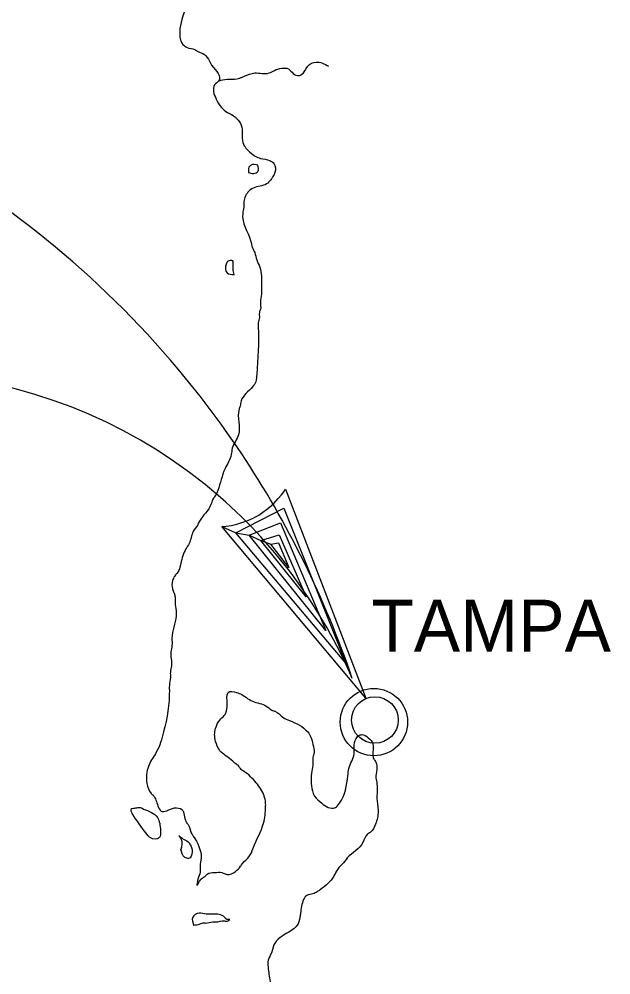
# Model space of a CAD drawing. Extents: x 492225 to 553725, y 1303773 to 1347273.
# Drawn here: x 540852 to 542273, y 1339012 to 1341307 of the extents above; entities that cross this region are included whole.
import ezdxf

# ---------------------------------------------------------------- set-up
doc = ezdxf.new("R2010")
doc.units = 0
for name, color, linetype in [('Level 1', 7, 'Continuous'), ('Level 62', 7, 'Continuous'), ('Level 63', 7, 'Continuous')]:
    doc.layers.add(name, color=color, linetype=linetype)

msp = doc.modelspace()

# ---------------------------------------------------------------- linework, layer by layer
at = {"layer": 'Level 1'}
msp.add_lwpolyline([(541339.016, 1340088.27), (541349.231, 1340089.057), (541362.236, 1340091.247), (541374.641, 1340093.745), (541384.496, 1340097.21), (541394.284, 1340100.187), (541401.514, 1340102.865), (541408.751, 1340105.962), (541413.919, 1340108.64), (541419.394, 1340111.437), (541427.539, 1340115.817), (541437.514, 1340122.5), (541446.386, 1340128.942), (541453.684, 1340134.837), (541464.019, 1340144.085), (541474.294, 1340155.762), (541482.139, 1340164.695), (541487.426, 1340171.812), (541491.619, 1340178.247), (541684.841, 1339675.987), (541339.016, 1340088.27), (541372.511, 1340073.135), (541487.546, 1340132.595), (541637.059, 1339760.557), (541372.511, 1340073.135), (541404.799, 1340067.48), (541479.701, 1340097.39), (541588.781, 1339838.932), (541404.799, 1340067.48), (541432.526, 1340054.895), (541476.236, 1340068.267), (541541.051, 1339919.917), (541432.526, 1340054.895), (541456.234, 1340046.255), (541475.081, 1340049.36), (541499.891, 1339989.772), (541456.234, 1340046.255)], dxfattribs=at)
msp.add_circle((541704.0334, 1339618.7885), 80.9269, dxfattribs=at)
for centre, radius, start, end in [((539463.2113, 1338980.6391), 2311.473, 33.7540933, 77.84251), ((540538.5032, 1339245.9527), 1211.5972, 48.8625679, 119.0596401), ((539463.2113, 1338980.6391), 2311.473, 18.7414572, 33.7540933), ((540538.5032, 1339245.9527), 1211.5972, 23.1999457, 48.8625679)]:
    msp.add_arc(centre, radius, start, end, dxfattribs=at)
at = {"layer": 'Level 62'}
msp.add_circle((541706.527, 1339623.7555), 55.9017, dxfattribs=at)
at = {"layer": 'Level 63'}
for points in [[(541252.812, 1341410.0055), (541254.062, 1341410.0055), (541255.312, 1341385.0055), (541252.812, 1341372.5055), (541252.812, 1341347.5055), (541242.812, 1341306.2555), (541237.812, 1341276.2555), (541245.312, 1341246.2555), (541255.312, 1341238.7555), (541274.062, 1341233.7555), (541281.562, 1341228.7555), (541289.062, 1341226.2555), (541314.062, 1341196.2555)], [(541332.812, 1341158.7555), (541336.562, 1341160.0055), (541356.562, 1341162.5055), (541369.062, 1341162.5055), (541417.812, 1341177.5055), (541452.812, 1341177.5055), (541465.312, 1341183.7555), (541482.812, 1341188.7555), (541495.312, 1341188.7555), (541520.312, 1341171.2555), (541530.312, 1341173.7555), (541545.312, 1341193.7555), (541565.312, 1341203.7555), (541580.312, 1341201.2555), (541595.312, 1341193.7555)], [(541314.062, 1341196.2555), (541331.562, 1341158.7555), (541321.562, 1341148.7555), (541319.062, 1341132.5055), (541325.312, 1341115.0055), (541337.812, 1341095.0055), (541352.812, 1341082.5055), (541370.312, 1341072.5055), (541375.312, 1341067.5055), (541385.312, 1341052.5055), (541387.812, 1341032.5055), (541387.812, 1341020.0055), (541392.812, 1341002.5055), (541401.562, 1340992.5055), (541419.062, 1340977.5055), (541431.562, 1340972.5055), (541454.062, 1340967.5055), (541464.062, 1340960.0055), (541466.562, 1340938.7555), (541461.562, 1340928.7555), (541456.562, 1340921.2555), (541446.562, 1340911.2555), (541414.062, 1340901.2555), (541401.562, 1340891.2555), (541391.562, 1340865.0055), (541391.562, 1340855.0055), (541389.062, 1340840.0055), (541407.812, 1340775.0055), (541412.812, 1340757.5055), (541417.812, 1340746.2555), (541422.812, 1340728.7555), (541430.312, 1340711.2555), (541434.062, 1340666.2555), (541434.062, 1340646.2555), (541431.562, 1340627.5055), (541431.562, 1340610.0055), (541429.062, 1340602.5055), (541429.062, 1340590.0055), (541426.562, 1340577.5055), (541426.562, 1340567.5055), (541422.812, 1340453.7555), (541420.312, 1340436.2555), (541412.812, 1340423.7555), (541385.312, 1340390.0055), (541382.812, 1340377.5055), (541380.312, 1340370.0055), (541379.062, 1340308.7555), (541364.062, 1340276.2555), (541361.562, 1340261.2555), (541346.562, 1340227.5055), (541329.062, 1340175.0055), (541321.562, 1340160.0055), (541316.562, 1340152.5055), (541312.812, 1340141.2555), (541285.312, 1340101.2555), (541280.312, 1340091.2555), (541270.312, 1340076.2555), (541260.312, 1340047.5055), (541252.812, 1340035.0055), (541240.312, 1340000.0055), (541235.312, 1339982.5055), (541225.312, 1339968.7555), (541220.312, 1339958.7555), (541220.312, 1339938.7555), (541224.062, 1339928.7555), (541226.562, 1339918.7555), (541226.562, 1339906.2555), (541229.062, 1339886.2555), (541229.062, 1339873.7555), (541219.062, 1339820.0055), (541219.062, 1339802.5055), (541216.562, 1339787.5055), (541217.812, 1339753.7555), (541215.312, 1339738.7555), (541215.312, 1339726.2555), (541212.812, 1339706.2555), (541212.812, 1339696.2555), (541199.062, 1339595.0055), (541181.562, 1339546.2555), (541164.062, 1339516.2555), (541159.062, 1339498.7555), (541159.062, 1339471.2555), (541169.062, 1339447.5055), (541174.062, 1339442.5055), (541185.312, 1339417.5055), (541192.812, 1339405.0055), (541225.312, 1339412.5055), (541242.812, 1339408.7555), (541252.812, 1339380.0055), (541257.812, 1339372.5055), (541265.312, 1339352.5055)], [(541425.312, 1340956.2555), (541409.062, 1340956.2555), (541404.062, 1340951.2555), (541402.812, 1340945.0055), (541402.812, 1340938.7555)], [(541402.812, 1340938.7555), (541415.312, 1340936.2555), (541425.312, 1340941.2555), (541425.312, 1340956.2555)], [(541354.062, 1340726.2555), (541349.062, 1340718.7555), (541351.562, 1340697.5055), (541369.062, 1340693.7555)], [(541354.062, 1340726.2555), (541364.062, 1340727.5055), (541365.312, 1340721.2555), (541365.312, 1340706.2555), (541367.812, 1340693.7555)], [(541265.312, 1339352.5055), (541270.312, 1339345.0055), (541289.062, 1339292.5055), (541286.562, 1339272.5055), (541286.562, 1339258.7555), (541281.562, 1339241.2555), (541279.062, 1339226.2555), (541289.062, 1339241.2555), (541299.062, 1339248.7555), (541304.062, 1339253.7555), (541321.562, 1339257.5055), (541339.062, 1339257.5055), (541351.562, 1339252.5055), (541371.562, 1339260.0055), (541384.062, 1339272.5055), (541389.062, 1339280.0055), (541404.062, 1339295.0055), (541414.062, 1339316.2555), (541439.062, 1339376.2555), (541444.062, 1339415.0055), (541444.062, 1339425.0055), (541432.812, 1339457.5055), (541407.812, 1339487.5055), (541392.812, 1339500.0055), (541385.312, 1339505.0055), (541377.812, 1339515.0055), (541370.312, 1339520.0055), (541365.312, 1339525.0055), (541334.062, 1339550.0055), (541324.062, 1339572.5055), (541321.562, 1339588.7555), (541324.062, 1339603.7555), (541334.062, 1339623.7555), (541344.062, 1339633.7555), (541351.562, 1339668.7555), (541351.562, 1339682.5055), (541354.062, 1339690.0055), (541374.062, 1339690.0055), (541386.562, 1339685.0055), (541401.562, 1339675.0055), (541416.562, 1339667.5055), (541434.062, 1339662.5055), (541449.062, 1339655.0055), (541459.062, 1339647.5055), (541466.562, 1339645.0055), (541486.562, 1339630.0055), (541501.562, 1339622.5055), (541545.312, 1339595.0055), (541552.812, 1339582.5055), (541557.812, 1339565.0055), (541560.312, 1339545.0055), (541557.812, 1339533.7555), (541557.812, 1339518.7555), (541555.312, 1339501.2555), (541556.562, 1339453.7555), (541561.562, 1339441.2555), (541579.062, 1339423.7555), (541594.062, 1339413.7555), (541611.562, 1339413.7555), (541621.562, 1339423.7555), (541641.562, 1339490.0055), (541644.062, 1339507.5055), (541656.562, 1339542.5055), (541657.812, 1339570.0055), (541667.812, 1339586.2555), (541675.312, 1339588.7555), (541690.312, 1339581.2555), (541701.562, 1339566.2555), (541701.562, 1339547.5055), (541704.062, 1339530.0055), (541709.062, 1339522.5055), (541709.062, 1339485.0055), (541711.562, 1339470.0055), (541711.562, 1339433.7555), (541712.812, 1339421.2555), (541712.812, 1339388.7555), (541707.812, 1339373.7555), (541695.312, 1339353.7555), (541687.812, 1339348.7555), (541677.812, 1339330.0055), (541640.312, 1339292.5055), (541627.812, 1339277.5055), (541622.812, 1339272.5055), (541612.812, 1339258.7555), (541607.812, 1339248.7555), (541575.312, 1339216.2555), (541567.812, 1339211.2555), (541557.812, 1339206.2555), (541542.812, 1339202.5055), (541535.312, 1339192.5055), (541527.812, 1339160.0055)], [(541151.562, 1339408.7555), (541144.062, 1339412.5055), (541136.562, 1339412.5055), (541126.562, 1339411.2555), (541120.312, 1339408.7555), (541121.562, 1339402.5055), (541127.812, 1339392.5055)], [(541150.312, 1339410.0055), (541184.062, 1339390.0055), (541191.562, 1339357.5055), (541189.062, 1339341.2555), (541166.562, 1339341.2555), (541161.562, 1339346.2555), (541127.812, 1339392.5055)], [(541235.312, 1339346.2555), (541245.312, 1339338.7555), (541257.812, 1339331.2555), (541262.812, 1339323.7555), (541267.812, 1339306.2555), (541259.062, 1339291.2555), (541250.312, 1339293.7555), (541240.312, 1339313.7555)], [(541236.562, 1339345.0055), (541240.312, 1339338.7555), (541242.812, 1339323.7555), (541240.312, 1339313.7555)], [(541357.812, 1339145.0055), (541350.312, 1339145.0055), (541345.312, 1339150.0055), (541316.562, 1339157.5055), (541301.562, 1339157.5055), (541284.062, 1339160.0055), (541269.062, 1339150.0055), (541271.562, 1339130.0055)], [(541271.562, 1339131.2555), (541285.312, 1339133.7555), (541291.562, 1339136.2555), (541300.312, 1339136.2555), (541316.562, 1339138.7555), (541324.062, 1339138.7555), (541345.312, 1339141.2555), (541354.062, 1339141.2555), (541357.812, 1339145.0055)], [(541527.812, 1339160.0055), (541526.562, 1339150.0055), (541519.062, 1339130.0055), (541511.562, 1339122.5055), (541479.062, 1339101.2555), (541464.062, 1339083.7555), (541456.562, 1339061.2555), (541451.562, 1339051.2555), (541451.562, 1339017.5055), (541454.062, 1339000.0055), (541461.562, 1338982.5055), (541466.562, 1338977.5055), (541471.562, 1338970.0055), (541482.812, 1338965.0055), (541512.812, 1338960.0055), (541595.312, 1338958.7555), (541605.312, 1338951.2555), (541610.312, 1338946.2555), (541615.312, 1338937.5055), (541620.312, 1338917.5055), (541585.312, 1338912.5055), (541572.812, 1338912.5055), (541537.812, 1338917.5055), (541525.312, 1338917.5055), (541507.812, 1338920.0055), (541442.812, 1338918.7555), (541430.312, 1338921.2555), (541394.062, 1338921.2555), (541381.562, 1338926.2555), (541364.062, 1338923.7555), (541349.062, 1338893.7555), (541352.812, 1338880.0055), (541360.312, 1338870.0055), (541380.312, 1338855.0055), (541387.812, 1338855.0055), (541402.812, 1338847.5055), (541417.812, 1338842.5055), (541435.312, 1338832.5055), (541465.312, 1338807.5055), (541476.562, 1338792.5055), (541501.562, 1338725.0055), (541509.062, 1338710.0055), (541525.312, 1338658.7555), (541530.312, 1338633.7555), (541537.812, 1338613.7555), (541555.312, 1338578.7555), (541560.312, 1338573.7555), (541577.812, 1338551.2555), (541589.062, 1338497.5055), (541586.562, 1338480.0055), (541586.562, 1338452.5055), (541600.312, 1338376.2555), (541605.312, 1338366.2555), (541615.312, 1338356.2555), (541640.312, 1338338.7555), (541650.312, 1338323.7555), (541650.312, 1338286.2555), (541655.312, 1338276.2555), (541661.562, 1338241.2555), (541669.062, 1338225.0055), (541676.562, 1338195.0055), (541689.062, 1338182.5055), (541709.062, 1338170.0055), (541740.312, 1338157.5055), (541757.812, 1338145.0055), (541790.312, 1338087.5055), (541797.812, 1338065.0055), (541806.562, 1338013.7555), (541806.562, 1337983.7555), (541809.062, 1337961.2555), (541809.062, 1337951.2555), (541819.062, 1337938.7555), (541826.562, 1337931.2555), (541834.062, 1337928.7555), (541849.062, 1337921.2555), (541856.562, 1337916.2555), (541885.312, 1337916.2555), (541905.312, 1337911.2555), (541942.812, 1337888.7555), (541962.812, 1337881.2555), (541982.812, 1337881.2555), (541995.312, 1337888.7555), (542000.312, 1337910.0055), (541997.812, 1337922.5055), (541997.812, 1337960.0055), (541995.312, 1337975.0055), (541995.312, 1337990.0055), (541986.562, 1338020.0055), (541976.562, 1338038.7555), (541946.562, 1338076.2555), (541931.562, 1338103.7555)]]:
    msp.add_spline(points, degree=3, dxfattribs=at)

# ---------------------------------------------------------------- texts
at = {"layer": 'Level 62'}
msp.add_text('TAMPA', height=125.0025, dxfattribs=at).set_placement((541697.812, 1339787.5055))

doc.saveas('drawing.dxf')
